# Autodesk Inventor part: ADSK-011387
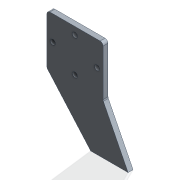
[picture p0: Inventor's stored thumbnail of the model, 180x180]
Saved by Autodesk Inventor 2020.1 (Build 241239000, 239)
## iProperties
Created: 2000-01
Part Number: ADSK-011387
Material: Pearson Aluminium
Document SubType Name: Modeling
Designer: sspink
Density: 2.71 g/cm^3
Appearance: Pearson-Aluminum
Mass: 565.39 g
Surface Area: 493.837 cm^2
Volume: 208.631 cm^3
Control State: 0
Checked Out: False
Master: False
Shininess: 35.0
Length Units: 11269
Angle Units: 11279
Time Units: 11290
Mass Units: 11283
Length Display Precision: 3
Angle Display Precision: 2
Compacted: True
Cutlength: 6.50
Material Desc: FLAT,ALUM,0.375X08.000
Material_number: A084929
Dimensions: 164,9x203x10 mm
Mass: 0,565 kg
DocNumber: ADSK-011387.ipt
Folder: 01 - Themengebiete\Simplification\01 - Packaging machine\
VDS_Category: 3D Komponenten
Density: 2.71
Volumn: 199.56140333374876
Area: 492.28407736009126
PropertySet Name: Model Information
Author: sspink
Revision Number: -
Title: plate
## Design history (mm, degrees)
node "Solide1"
  node "Extrusion1" dims "d2" = 10, "d3" = 0
  node "Hole1" dims "d11" = 10.31875, "d12" = 9.525, "d13" = 6.35, "d14" = 60 deg, "d15" = 19.05, "d16" = 118 deg
  node "Fillet1" dims "d27" = 6
sketch "Sketch1"
  geometry: L1 (114, 0)-(0, 0); L2 (0, 0)-(0, -101.5); L3 (0, -101.5)-(88.9, -203); L4 (114, -101.5)-(164.9, -203); L5 (114, 0)-(114, -101.5); L6 (88.9, -203)-(164.9, -203); 1 further point
  constraints: 12 end point, 2 perpendicular, 1 coincident, 1 horizontal, 1 parallel
  dimensions: "d18" = 88.9 distance from line of L3.end L2; "d19" = 203 distance between parallel lines of L6 L1; "d20" = 101.5 distance of L1.end L2.end; "d21" = 114 distance of L1.start L1.end; "d26" = 76 distance of L3.end L4.end
workplane "Work Plane1"
sketch "Sketch2"
  geometry: L1 (-114, 0)-(0, 0) reference; L2 (-88.9, -203)-(-164.9, -203) reference; L3 (-114, -101.5)-(0, -101.5); L4 (-57, -101.5)-(-57, 0); L5 (0, 0)-(0, -101.5) reference; L6 (-57, 0)-(-57, -15); C1 r 4.594 at (-57, -15); C2 r 4.594 at (-57, -85); C3 r 4.594 at (-102, -50); C4 r 4.594 at (-12, -50); 3 further points
  constraints: 6 end point, 4 centre point, 4 coincident, 2 midpoint, 1 collinear, 1 horizontal alignment, 1 parallel, 1 vertical alignment
  dimensions: "d5" = 14.99997 distance from line of C1.centre L1; "d6" = 84.99983 distance from line of C2.centre L1; "d23" = 49.9999 distance from line of C3.centre L1; "d24" = 89.99982 distance of C4.centre C3.centre; "d25" = 44.99991 horizontal distance of L4.end C3.centre (= 0.5 x d24)
workplane "Work Plane2"
workplane "Arbeitsebene3"
node "Corps solides"
node "Corps surfaciques"
other parameters: "d17" = 142.875, "d22" = -57.15
